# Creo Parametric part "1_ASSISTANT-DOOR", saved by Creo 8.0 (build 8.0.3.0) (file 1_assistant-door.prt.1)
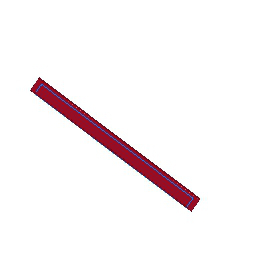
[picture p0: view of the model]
Units: millimeter Newton Second (mmNs); MM, TONNE, SECS

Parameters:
  SMT_DFLT_BEND_REL_LENGTH_TYPE = "Through All"

Other parameters: SMT_THICKNESS, SMT_PART_BEND_ALLOWANCE_FACTOR, SMT_DFLT_BEND_RADIUS, SMT_DFLT_BEND_ANGLE, SMT_DFLT_CRNR_REL_WIDTH, SMT_DFLT_CRNR_REL_DEPTH, SMT_DFLT_BEND_REL_WIDTH, SMT_DFLT_BEND_REL_DEPTH, SMT_DFLT_BEND_REL_LENGTH, SMT_DFLT_BEND_REL_ANGLE, SMT_GAP, SMT_DFLT_EDGE_TREA_WIDTH, SMT_DFLT_MITER_CUT_WIDTH, SMT_DFLT_MITER_CUT_OFFSET

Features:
  1. datum plane "DTM1"
  2. datum plane "DTM2"
  3. datum plane "DTM3"
  4. coordinate system
  5. datum plane "DTM7"
  6. datum plane "DTM11"
  7. protrusion
  8. round
  9. cut
  10. cut
  11. round
  12. cut
  13. datum plane "DTM5"
  14. round
  15. cut
  16. cut
  17. round
  18. cut
  19. chamfer
  20. cut
  21. chamfer
  22. curve

Other named items: CS0

Layers: 0_ALL_AXIS, 0_ALL_CSYS, 0_ALL_CURVES, 0_ALL_PLANES, 0_ALL_POINTS, 0_ALL_SURFS, ASSISTANT-DOOR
